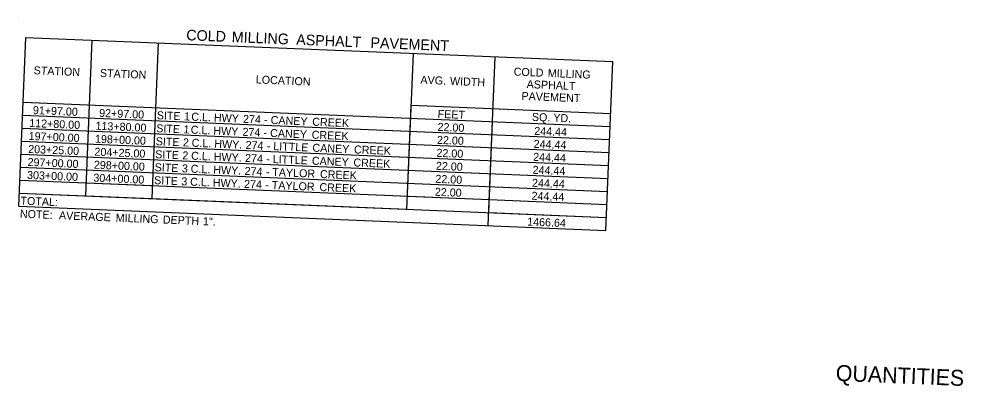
# Model space of a CAD drawing. Extents: x 1164179 to 1171425, y 1655958 to 1657208.
# Drawn here: x 1165001 to 1165709, y 1656192 to 1656468 of the extents above; entities that cross this region are included whole.
import ezdxf

# ---------------------------------------------------------------- set-up
doc = ezdxf.new("R2010")
doc.units = 0
doc.layers.add('Default', color=7, linetype='Continuous')
doc.layers.add('R_Border Prem', color=7, linetype='Continuous')

msp = doc.modelspace()

# ---------------------------------------------------------------- linework, layer by layer
at = {"layer": 'Default'}
for p, q in [((1165001.33, 1656467.73), (1165001.33, 1656467.73)), ((1165001.38, 1656327.2), (1165006.61, 1656453.85)), ((1165001.38, 1656327.2), (1165006.61, 1656453.85)), ((1165006.61, 1656453.85), (1165446.45, 1656435.65)), ((1165051.46, 1656334.89), (1165056.3, 1656451.79)), ((1165101.14, 1656332.83), (1165105.98, 1656449.73)), ((1165292.08, 1656324.94), (1165296.92, 1656441.84)), ((1165353.05, 1656312.66), (1165358.29, 1656439.3)), ((1165441.21, 1656309.01), (1165446.45, 1656435.65)), ((1165441.21, 1656309.01), (1165446.45, 1656435.65)), ((1165004.6, 1656405.14), (1165444.44, 1656386.94)), ((1165051.46, 1656334.89), (1165054.28, 1656403.08)), ((1165101.14, 1656332.83), (1165103.96, 1656401.03)), ((1165292.08, 1656324.94), (1165295.3, 1656402.87)), ((1165295.3, 1656402.87), (1165444.84, 1656396.68)), ((1165004.2, 1656395.4), (1165444.03, 1656377.2)), ((1165003.79, 1656385.65), (1165443.63, 1656367.46)), ((1165353.45, 1656322.4), (1165356.27, 1656390.59)), ((1165003.39, 1656375.91), (1165443.23, 1656357.72)), ((1165002.99, 1656366.17), (1165442.82, 1656347.97)), ((1165002.58, 1656356.43), (1165442.42, 1656338.23)), ((1165002.18, 1656346.69), (1165101.55, 1656342.58)), ((1165002.18, 1656346.69), (1165051.86, 1656344.63)), ((1165051.86, 1656344.63), (1165353.86, 1656332.14)), ((1165001.78, 1656336.95), (1165051.46, 1656334.89)), ((1165001.78, 1656336.95), (1165441.61, 1656318.75)), ((1165051.46, 1656334.89), (1165101.14, 1656332.83)), ((1165101.14, 1656332.83), (1165292.08, 1656324.94)), ((1165292.48, 1656334.68), (1165353.86, 1656332.14)), ((1165353.86, 1656332.14), (1165442.02, 1656328.49)), ((1165001.38, 1656327.2), (1165441.21, 1656309.01)), ((1165353.45, 1656322.4), (1165441.61, 1656318.75))]:
    msp.add_line(p, q, dxfattribs=at)

# ---------------------------------------------------------------- texts
for s, height, p in [('COLD', 8, (1165126.66, 1656451.71)), (' MILLING', 8, (1165157.75, 1656450.42)), (' ASPHALT', 8, (1165206.08, 1656448.42)), (' PAVEMENT', 8, (1165261.7, 1656446.12)), ('STATION', 6, (1165012.28, 1656426.21)), ('STATION', 6, (1165061.96, 1656424.16)), ('COLD', 6, (1165372.03, 1656425.22)), (' MILLING', 6, (1165395.35, 1656424.25)), ('LOCATION', 6, (1165178.78, 1656419.32)), ('AVG.', 6, (1165302.16, 1656419.1)), (' WIDTH', 6, (1165322.06, 1656418.28)), ('ASPHALT', 6, (1165381.75, 1656415.81)), ('PAVEMENT', 6, (1165377.88, 1656406.96)), ('91+97.00', 6, (1165011.71, 1656396.29)), ('92+97.00', 6, (1165061.39, 1656394.23)), ('SITE', 6, (1165104.59, 1656392.44)), ('FEET', 6, (1165315.02, 1656393.5)), ('112+80.00', 6, (1165008.98, 1656386.64)), (' 1', 6, (1165122.76, 1656391.69)), (' C.L.', 6, (1165128.2, 1656391.47)), (' HWY', 6, (1165145.15, 1656390.77)), (' 274', 6, (1165166.96, 1656389.86)), (' -', 6, (1165182.84, 1656389.21)), (' CANEY', 6, (1165187.7, 1656389.01)), (' CREEK', 6, (1165218.82, 1656387.72)), ('SQ.', 6, (1165385.65, 1656391.25)), (' YD.', 6, (1165399.5, 1656390.68)), ('113+80.00', 6, (1165058.66, 1656384.58)), ('SITE', 6, (1165104.18, 1656382.7)), (' 1', 6, (1165122.35, 1656381.95)), (' C.L.', 6, (1165127.8, 1656381.72)), (' HWY', 6, (1165144.75, 1656381.02)), (' 274', 6, (1165166.55, 1656380.12)), (' CANEY', 6, (1165187.29, 1656379.26)), ('22.00', 6, (1165314.96, 1656383.74)), ('244.44', 6, (1165387.4, 1656380.74)), ('197+00.00', 6, (1165008.58, 1656376.9)), ('198+00.00', 6, (1165058.26, 1656374.84)), ('SITE', 6, (1165103.78, 1656372.96)), (' 2', 6, (1165121.95, 1656372.21)), (' C.L.', 6, (1165128.49, 1656371.94)), (' -', 6, (1165182.44, 1656379.46)), (' CREEK', 6, (1165218.42, 1656377.98)), ('22.00', 6, (1165314.56, 1656374)), ('203+25.00', 6, (1165008.18, 1656367.16)), ('204+25.00', 6, (1165057.86, 1656365.1)), (' HWY.', 6, (1165145.44, 1656371.24)), (' 274', 6, (1165168.9, 1656370.27)), (' -', 6, (1165184.79, 1656369.61)), (' LITTLE', 6, (1165189.64, 1656369.41)), (' CANEY', 6, (1165218.98, 1656368.19)), (' CREEK', 6, (1165250.11, 1656366.91)), ('22.00', 6, (1165314.15, 1656364.26)), ('244.44', 6, (1165387, 1656371)), ('297+00.00', 6, (1165007.77, 1656357.41)), ('SITE', 6, (1165103.38, 1656363.22)), (' 2', 6, (1165121.55, 1656362.47)), (' C.L.', 6, (1165128.09, 1656362.2)), (' HWY.', 6, (1165145.04, 1656361.49)), (' 274', 6, (1165168.5, 1656360.52)), (' LITTLE', 6, (1165189.24, 1656359.67)), (' CANEY', 6, (1165218.58, 1656358.45)), (' CREEK', 6, (1165249.71, 1656357.16)), ('244.44', 6, (1165386.6, 1656361.26)), ('298+00.00', 6, (1165057.45, 1656355.36)), ('SITE', 6, (1165102.97, 1656353.48)), (' 3', 6, (1165121.15, 1656352.72)), (' C.L.', 6, (1165127.75, 1656352.45)), (' HWY.', 6, (1165144.7, 1656351.75)), (' 274', 6, (1165168.16, 1656350.78)), (' -', 6, (1165184.39, 1656359.87)), ('22.00', 6, (1165313.75, 1656354.52)), ('244.44', 6, (1165386.19, 1656351.52)), ('303+00.00', 6, (1165007.37, 1656347.67)), ('304+00.00', 6, (1165057.05, 1656345.62)), ('SITE', 6, (1165102.57, 1656343.73)), (' 3', 6, (1165120.74, 1656342.98)), (' -', 6, (1165184.05, 1656350.12)), (' TAYLOR', 6, (1165188.9, 1656349.92)), (' CREEK', 6, (1165224.63, 1656348.44)), ('22.00', 6, (1165313.35, 1656344.77)), (' C.L.', 6, (1165127.34, 1656342.71)), (' HWY.', 6, (1165144.3, 1656342.01)), (' 274', 6, (1165167.76, 1656341.04)), (' -', 6, (1165183.65, 1656340.38)), (' TAYLOR', 6, (1165188.5, 1656340.18)), (' CREEK', 6, (1165224.23, 1656338.7)), ('244.44', 6, (1165385.79, 1656341.78)), ('22.00', 6, (1165312.94, 1656335.03)), ('244.44', 6, (1165385.39, 1656332.04)), ('TOTAL:', 6, (1165002.4, 1656328.36)), ('NOTE:', 6, (1165002, 1656318.62)), ('  AVERAGE', 6, (1165026.86, 1656317.59)), (' MILLING', 6, (1165071.57, 1656315.74)), (' DEPTH', 6, (1165106.88, 1656314.28)), (' 1".', 6, (1165136.92, 1656313.04)), ('1466.64', 6, (1165382.14, 1656312.65))]:
    msp.add_text(s, height=height, rotation=357.63112, dxfattribs=at).set_placement(p)
at = {"layer": 'R_Border Prem'}
msp.add_text('QUANTITIES', height=12, rotation=357.63112, dxfattribs=at).set_placement((1165613.27, 1656196.18))

doc.saveas('drawing.dxf')
